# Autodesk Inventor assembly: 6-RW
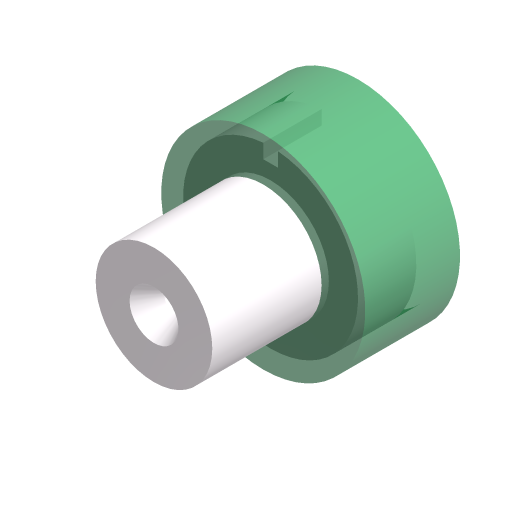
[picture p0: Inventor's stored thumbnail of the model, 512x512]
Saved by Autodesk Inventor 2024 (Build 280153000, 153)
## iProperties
Created: 2023-03
Part Number: 6-RW
Document SubType Name: Assembly
Designer: Andrzej Jaskulski
Manufacturer: Standard
Standards Organization: Custom
Checked By: A.J.
Engr Approved By: Andrzej Jaskulski
Mfg Approved By: Andrzej Jaskulski
Authority: A.J.
Company: ATC
Title: A.J.: Kurs R2024-MEP
Author: Andrzej Jaskulski
Revision Number: 1/24
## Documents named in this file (3)
- C:\Users\AndJas\Documents\R2024-MEP\Obszar roboczy\6-RW.iam
- C:\Users\AndJas\Documents\R2024-MEP\Obszar roboczy\6-RW-1.ipt
- C:\Users\AndJas\Documents\R2024-MEP\Obszar roboczy\6-RW-2.ipt
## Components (2 placed, 2 different names)
1. 6-RW-1:1 — Wstaw:1
2. 6-RW-2:1 — Wstaw:1
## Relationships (1: Insert 1)
- Wstaw:1 [Insert]: 6-RW-1:1 ↔ 6-RW-2:1
